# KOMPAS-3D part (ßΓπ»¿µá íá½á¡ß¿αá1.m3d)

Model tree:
1. Эскиз:1
2. Операция выдавливания:1
     Расстояние 1 = 16
3. Эскиз:3
4. Операция выдавливания:2
     Расстояние 1 = 16; Расстояние 2 = 4
5. Эскиз:12
6. Операция выдавливания:3
     Расстояние 1 = 9; Расстояние 2 = 9
7. Эскиз:13
8. Вырезать элемент выдавливания:9
     Расстояние 1 = 18
9. Эскиз:14
10. Операция выдавливания:4
     Расстояние 1 = 9; Расстояние 2 = 16
11. Эскиз:15
12. Вырезать элемент выдавливания:10
     Расстояние 1 = 2
13. Эскиз:16
14. Вырезать элемент выдавливания:11
     Расстояние 1 = 16
15. Эскиз:17
16. Вырезать элемент выдавливания:12
     Расстояние 1 = 2
17. Скругление:8
     Радиус = 0.5
18. Скругление:9
     Радиус = 0.5
19. Скругление:10
     Радиус = 0.2
20. Скругление:11
     Радиус = 0.5
21. Скругление:12
     Радиус = 0.2
22. Эскиз:18
23. Вырезать элемент выдавливания:13
     Расстояние 1 = 4

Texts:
  ступица балансира 1
  Сплав АЛ8  ГОСТ 1583-93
